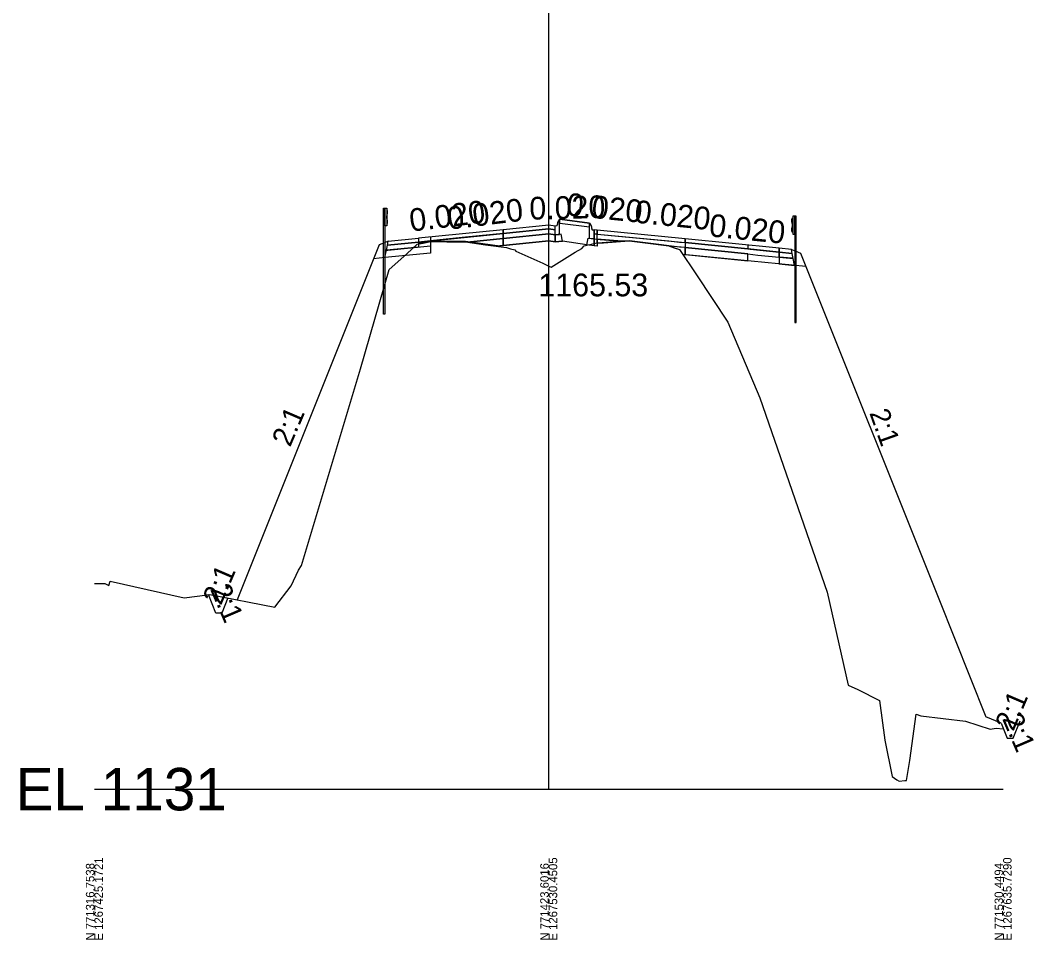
# Model space of a CAD drawing. Extents: x -3833 to 1267678, y -522 to 773248.
# Drawn here: x 4657.2 to 4991.8, y -49.7 to 253.8 of the extents above; entities that cross this region are included whole.
import ezdxf

# ---------------------------------------------------------------- set-up
doc = ezdxf.new("R2010")
doc.units = 0
for name, color, linetype in [('Exist Utilities Water UG Line SUE LOS B', 7, 'Continuous'), ('Prop Drainage Structure Catch Basin Grate 840 03E CELL', 7, 'Continuous'), ('Prop Drainage Structure Catch Basin Grate 840 03E Label', 7, 'Continuous'), ('Prop Drainage Structure Catch Basin Grate 840 03F CELL', 7, 'Continuous'), ('Prop Drainage Structure Catch Basin Grate 840 03F Label', 7, 'Continuous'), ('Prop Drainage Structure Catch Basin Grate 840 03G CELL', 7, 'Continuous'), ('Prop Drainage Structure Catch Basin Grate 840 03G Label', 7, 'Continuous'), ('Prop Drainage Structure Drop Inlet Grate 2 Narrow Slots and Flat Grates 840 29 CELL', 7, 'Continuous'), ('Prop Drainage Structure Drop Inlet Grate 2 Narrow Slots and Flat Grates 840 29 Label', 7, 'Continuous'), ('Prop Drainage Structure Headwall CELL', 7, 'Continuous'), ('Prop Drainage Structure Junction Box with Manhole CELL', 7, 'Continuous'), ('Prop Drainage Structure Junction Box with Manhole Label', 7, 'Continuous'), ('Prop Drainage Structure Junction Box with Manhole TB Label', 7, 'Continuous'), ('Prop Drainage Structure Pipe RCP 18in Class III', 7, 'Continuous'), ('Prop Drainage Structure Pipe RCP 18in Class III Label', 7, 'Continuous'), ('Prop Drainage Structure Pipe Removal', 7, 'Continuous'), ('Prop Drainage Structure Removal Label', 7, 'Continuous'), ('Prop Earthen Structure Ditch Flow Line', 7, 'Continuous'), ('Scratch_Level_3', 7, 'Continuous')]:
    doc.layers.add(name, color=color, linetype=linetype)

msp = doc.modelspace()

# ---------------------------------------------------------------- linework, layer by layer
at = {"layer": 'Prop Drainage Structure Catch Basin Grate 840 03F CELL'}
for p, q in [((4835.26, 188.09), (4835.35, 188.08)), ((4835.35, 188.08), (4845.16, 186.8)), ((4845.16, 186.8), (4845.16, 186.8)), ((4778.67, 180.84), (4777.47, 180.37)), ((4775.67, 179.64), (4728.82, 62.51)), ((4777.47, 180.37), (4775.67, 179.64)), ((4911.8, 178.13), (4913, 177.65)), ((4913, 177.65), (4914.8, 176.93)), ((4914.8, 176.93), (4960.45, 62.81)), ((4721.74, 58.12), (4719.3, 64.22)), ((4725.74, 63.12), (4723.74, 58.12)), ((4960.45, 62.81), (4976.02, 23.88)), ((4723.74, 58.12), (4721.74, 58.12)), ((4981.02, 21.79), (4976.02, 23.88)), ((4981.02, 21.79), (4983.02, 16.79)), ((4985.02, 16.79), (4987.32, 22.53)), ((4983.02, 16.79), (4985.02, 16.79))]:
    msp.add_line(p, q, dxfattribs=at)
at = {"layer": 'Prop Drainage Structure Catch Basin Grate 840 03F Label'}
for p, q in [((4792.67, 180.99), (4788.67, 180.59)), ((4788.67, 180.21), (4792.61, 180.91)), ((4792.61, 180.91), (4793.67, 180.91)), ((4793.67, 181.09), (4792.67, 180.99)), ((4804.23, 182.15), (4793.67, 181.09)), ((4793.67, 181.09), (4793.67, 181.09)), ((4793.67, 180.91), (4793.67, 180.91)), ((4793.67, 180.91), (4804.23, 180.86)), ((4816.67, 183.39), (4804.23, 182.15)), ((4804.23, 182.15), (4804.23, 182.15)), ((4804.23, 182.15), (4804.23, 182.15)), ((4804.23, 180.86), (4804.23, 180.86)), ((4804.23, 180.86), (4804.23, 180.86)), ((4804.23, 180.86), (4805.81, 180.64)), ((4805.81, 180.64), (4816.67, 181.73)), ((4816.67, 181.73), (4816.67, 183.39)), ((4816.67, 183.39), (4816.67, 183.39)), ((4816.67, 181.73), (4816.67, 181.73)), ((4847.65, 181.55), (4847.65, 183.22)), ((4847.65, 183.22), (4847.65, 183.22)), ((4847.65, 183.22), (4847.65, 183.22)), ((4847.65, 183.22), (4855.98, 182.46)), ((4855.77, 180.82), (4847.65, 181.55)), ((4847.65, 181.55), (4847.65, 181.55)), ((4847.65, 181.55), (4847.65, 181.55)), ((4847.65, 181.55), (4847.65, 181.55)), ((4847.65, 181.55), (4847.65, 181.55)), ((4855.98, 180.83), (4855.77, 180.82)), ((4855.98, 182.46), (4855.98, 182.46)), ((4855.98, 182.46), (4858.31, 182.23)), ((4858.31, 181.02), (4855.98, 180.83)), ((4855.98, 180.83), (4855.98, 180.83)), ((4858.31, 182.23), (4858.31, 182.23)), ((4858.31, 182.23), (4868.88, 181.17)), ((4868.88, 179.63), (4858.31, 181.02)), ((4858.31, 181.02), (4858.31, 181.02)), ((4868.88, 181.17), (4868.88, 181.17)), ((4868.88, 181.17), (4871.31, 180.93)), ((4871.31, 180.93), (4871.31, 180.93)), ((4871.31, 180.93), (4871.31, 180.93)), ((4871.31, 180.93), (4872.2, 180.84)), ((4872.2, 180.84), (4872.2, 180.84)), ((4872.2, 180.84), (4874.88, 180.57)), ((4778.07, 177.87), (4778.41, 179.57)), ((4788.67, 178.93), (4778.07, 177.87)), ((4778.07, 177.87), (4778.07, 177.87)), ((4778.07, 177.87), (4778.07, 177.87)), ((4778.41, 179.57), (4788.67, 180.59)), ((4778.41, 179.57), (4778.41, 179.57)), ((4788.67, 180.59), (4788.67, 178.93)), ((4788.67, 180.59), (4788.67, 180.21)), ((4788.67, 180.21), (4788.67, 180.21)), ((4788.67, 178.93), (4788.67, 178.93)), ((4805.81, 180.64), (4805.81, 180.64)), ((4805.81, 180.64), (4805.81, 180.64)), ((4871.31, 179.31), (4868.88, 179.63)), ((4868.88, 179.63), (4868.88, 179.63)), ((4871.51, 179.24), (4871.31, 179.31)), ((4871.31, 179.31), (4871.31, 179.31)), ((4871.31, 179.31), (4871.31, 179.31)), ((4872.2, 179.17), (4871.51, 179.24)), ((4871.51, 179.24), (4871.51, 179.24)), ((4874.88, 178.9), (4872.2, 179.17)), ((4872.2, 179.17), (4872.2, 179.17)), ((4874.88, 180.57), (4876.67, 180.39)), ((4876.67, 178.73), (4874.88, 178.9)), ((4876.67, 180.39), (4876.67, 180.39)), ((4876.67, 180.39), (4876.67, 178.73)), ((4876.67, 178.73), (4876.67, 178.73)), ((4876.67, 178.73), (4876.67, 178.73)), ((4907.73, 177.29), (4907.73, 175.64)), ((4912.06, 176.85), (4907.73, 177.29)), ((4907.73, 175.64), (4912.39, 175.17)), ((4912.39, 175.17), (4912.06, 176.85))]:
    msp.add_line(p, q, dxfattribs=at)
at = {"layer": 'Prop Drainage Structure Catch Basin Grate 840 03G CELL'}
for p, q in [((4777.6, 175.53), (4778.07, 177.87)), ((4778.07, 177.87), (4778.57, 177.92)), ((4778.57, 177.92), (4792.67, 179.33)), ((4792.67, 176.86), (4777.6, 175.53)), ((4907.73, 175.64), (4907.73, 173.34)), ((4911.89, 175.22), (4907.73, 175.64)), ((4912.39, 175.17), (4911.89, 175.22)), ((4912.86, 172.83), (4912.39, 175.17)), ((4907.73, 173.34), (4912.86, 172.83))]:
    msp.add_line(p, q, dxfattribs=at)
at = {"layer": 'Prop Drainage Structure Catch Basin Grate 840 03G Label'}
for p, q in [((4816.67, 184.64), (4816.67, 183.39)), ((4792.67, 182.24), (4792.67, 180.99)), ((4897.37, 179.57), (4897.37, 178.32))]:
    msp.add_line(p, q, dxfattribs=at)
at = {"layer": 'Prop Drainage Structure Drop Inlet Grate 2 Narrow Slots and Flat Grates 840 29 CELL'}
for p, q in [((4831.67, 0), (4831.67, 543.04)), ((4681.67, 0), (4831.67, 0)), ((4831.67, 0), (4981.67, 0))]:
    msp.add_line(p, q, dxfattribs=at)
at = {"layer": 'Prop Drainage Structure Drop Inlet Grate 2 Narrow Slots and Flat Grates 840 29 Label'}
msp.add_lwpolyline([(4681.67, 67.87), (4685.08, 67.9), (4686.41, 67.2), (4686.83, 68.69), (4711.32, 63.17), (4715.59, 63.71), (4719.78, 64.29), (4741.23, 60.07), (4746.62, 67.08), (4749.07, 72.32), (4750.02, 73.84), (4769.57, 138.75), (4778.99, 171.55), (4784.84, 176.67), (4788.2, 179.85), (4790.17, 180.2), (4792.59, 180.71), (4797.99, 180.69), (4804.16, 180.64), (4810.82, 179.7), (4817.76, 178.73), (4819.09, 178.36), (4820.47, 177.99), (4820.86, 177.52), (4829.67, 173.63), (4831.67, 172.67), (4832.51, 172.27), (4840.38, 177.23), (4842.55, 178.49), (4843.36, 179.33), (4846.15, 179.96), (4847.07, 180.16), (4849.79, 180.37), (4858.18, 181.01), (4862.6, 180.48), (4871.31, 179.33), (4873.11, 178.68), (4874.88, 178.08), (4880.41, 169.77), (4890.78, 154.15), (4901.31, 129.2), (4923.57, 65.04), (4930.56, 34.37), (4933.69, 32.87), (4940.89, 29.24), (4942.62, 16.15), (4945.03, 4.22), (4946.54, 3.08), (4947.36, 2.64), (4949.25, 2.86), (4949.83, 2.83), (4950.89, 9.44), (4953.02, 24.71), (4954.47, 24.18), (4969.23, 22.42), (4977.37, 19.82), (4979.39, 20.14), (4981.67, 19.86)], dxfattribs=at)
at = {"layer": 'Prop Drainage Structure Headwall CELL'}
for p, q in [((4831.67, 186.14), (4816.67, 184.64)), ((4816.67, 183.39), (4831.67, 184.89)), ((4816.67, 184.64), (4816.67, 184.64)), ((4816.67, 184.64), (4816.67, 183.39)), ((4833.76, 185.86), (4831.67, 186.14)), ((4831.67, 184.89), (4833.76, 184.61)), ((4833.76, 184.61), (4833.76, 185.86)), ((4833.76, 185.86), (4833.76, 185.86)), ((4833.76, 184.61), (4833.76, 184.61)), ((4833.76, 184.61), (4833.76, 184.61)), ((4846.66, 184.57), (4846.66, 183.32)), ((4847.65, 184.47), (4846.66, 184.57)), ((4847.65, 183.22), (4847.65, 184.47)), ((4847.65, 184.47), (4847.65, 184.47)), ((4778.41, 179.57), (4778.67, 180.84)), ((4778.67, 180.84), (4788.67, 181.84)), ((4778.67, 180.84), (4778.67, 180.84)), ((4788.67, 181.84), (4788.67, 180.59)), ((4816.67, 183.39), (4816.67, 183.39)), ((4816.67, 183.39), (4816.67, 183.39)), ((4846.66, 183.32), (4847.65, 183.22)), ((4788.67, 180.59), (4778.41, 179.57)), ((4778.41, 179.57), (4778.41, 179.57)), ((4778.41, 179.57), (4778.41, 179.57)), ((4788.67, 180.59), (4788.67, 180.59)), ((4907.73, 178.54), (4907.73, 177.29)), ((4911.8, 178.13), (4907.73, 178.54)), ((4912.06, 176.85), (4911.8, 178.13)), ((4907.73, 177.29), (4912.06, 176.85))]:
    msp.add_line(p, q, dxfattribs=at)
at = {"layer": 'Prop Drainage Structure Junction Box with Manhole CELL'}
for p, q in [((4815.49, 181.61), (4805.81, 180.64)), ((4816.67, 181.73), (4815.49, 181.61)), ((4831.67, 183.24), (4816.67, 181.73)), ((4816.67, 181.73), (4816.67, 181.74)), ((4816.67, 181.74), (4816.68, 179.43)), ((4816.67, 181.73), (4816.67, 181.73)), ((4816.68, 179.43), (4816.67, 181.73)), ((4816.67, 181.73), (4816.67, 181.73)), ((4816.67, 181.73), (4816.67, 181.73)), ((4816.68, 179.43), (4831.67, 180.95)), ((4833.76, 182.95), (4831.67, 183.24)), ((4831.67, 180.95), (4833.75, 180.65)), ((4833.75, 180.65), (4833.76, 182.95)), ((4833.76, 182.95), (4833.75, 180.65)), ((4833.75, 180.65), (4836.18, 180.84)), ((4835.76, 183.14), (4833.76, 182.95)), ((4833.76, 182.95), (4833.76, 182.95)), ((4833.76, 182.95), (4833.76, 182.95)), ((4836.18, 180.84), (4835.76, 183.14)), ((4844.21, 179.68), (4844.66, 181.85)), ((4844.66, 181.85), (4846.66, 181.65)), ((4846.65, 179.36), (4846.66, 181.65)), ((4846.66, 181.65), (4846.65, 179.36)), ((4846.66, 181.65), (4847.65, 181.55)), ((4847.65, 181.55), (4847.64, 179.26)), ((4847.64, 180.19), (4847.65, 181.55)), ((4847.65, 181.55), (4848.63, 181.45)), ((4848.63, 181.45), (4855.77, 180.82)), ((4855.77, 180.82), (4849.35, 180.32)), ((4805.81, 180.64), (4805.81, 180.64)), ((4805.81, 180.64), (4805.81, 180.64)), ((4805.81, 180.64), (4808.37, 180.3)), ((4808.37, 180.3), (4808.37, 180.3)), ((4808.37, 180.28), (4808.37, 180.28)), ((4808.37, 180.28), (4809.87, 180.07)), ((4809.87, 180.07), (4815.49, 179.29)), ((4815.49, 179.29), (4816.68, 179.43)), ((4816.68, 179.43), (4816.68, 179.43)), ((4816.68, 179.43), (4816.68, 179.43)), ((4816.68, 179.43), (4816.68, 179.43)), ((4816.68, 179.43), (4816.68, 179.43)), ((4816.68, 179.43), (4816.68, 179.43)), ((4833.75, 180.65), (4833.75, 180.65)), ((4833.75, 180.65), (4833.75, 180.65)), ((4833.75, 180.65), (4833.75, 180.65)), ((4833.75, 180.65), (4833.75, 180.65)), ((4846.65, 179.36), (4844.21, 179.68)), ((4844.21, 179.68), (4844.21, 179.68)), ((4847.64, 179.26), (4846.65, 179.36)), ((4849.35, 180.32), (4847.64, 180.19)), ((4875.42, 178.85), (4871.56, 179.24)), ((4871.56, 179.24), (4874.88, 178.1)), ((4874.88, 178.1), (4875.93, 176.52)), ((4876.67, 178.73), (4875.42, 178.85)), ((4876.67, 178.74), (4876.67, 176.45)), ((4897.37, 176.67), (4876.67, 178.74)), ((4876.67, 176.45), (4876.67, 178.73)), ((4875.93, 176.52), (4876.67, 176.45)), ((4876.67, 176.45), (4897.37, 174.38)), ((4897.37, 174.38), (4897.37, 176.67))]:
    msp.add_line(p, q, dxfattribs=at)
at = {"layer": 'Prop Drainage Structure Junction Box with Manhole Label'}
for p, q in [((4831.67, 184.89), (4816.67, 183.39)), ((4833.76, 184.61), (4831.67, 184.89)), ((4833.76, 182.95), (4833.76, 184.61)), ((4833.76, 184.61), (4833.76, 184.61)), ((4816.67, 183.39), (4816.67, 183.39)), ((4816.67, 183.39), (4816.67, 181.74)), ((4816.67, 181.73), (4831.67, 183.24)), ((4816.67, 181.74), (4816.67, 181.74)), ((4816.67, 181.74), (4816.67, 181.73)), ((4816.67, 181.73), (4816.67, 181.73)), ((4831.67, 183.24), (4833.76, 182.95)), ((4833.76, 182.95), (4833.76, 182.95)), ((4833.76, 182.95), (4833.76, 182.95)), ((4833.76, 182.95), (4833.76, 182.95)), ((4846.66, 183.32), (4846.66, 181.65)), ((4847.65, 183.22), (4846.66, 183.32)), ((4846.66, 181.65), (4847.65, 181.55)), ((4847.65, 181.55), (4847.65, 183.22)), ((4847.65, 183.22), (4847.65, 183.22)), ((4847.65, 181.55), (4847.65, 181.55)), ((4876.67, 180.39), (4876.67, 178.74)), ((4897.37, 178.32), (4876.67, 180.39)), ((4876.67, 178.74), (4897.37, 176.67)), ((4907.73, 177.29), (4897.37, 178.32)), ((4897.37, 176.67), (4900.68, 176.28)), ((4900.68, 176.28), (4907.73, 175.64)), ((4907.73, 175.64), (4907.73, 177.29))]:
    msp.add_line(p, q, dxfattribs=at)
at = {"layer": 'Prop Drainage Structure Junction Box with Manhole TB Label'}
for p, q in [((4792.67, 180.91), (4792.67, 176.86)), ((4831.67, 180.95), (4815.49, 179.29)), ((4833.75, 180.65), (4831.67, 180.95)), ((4836.18, 180.84), (4833.75, 180.65)), ((4844.21, 179.68), (4836.18, 180.84)), ((4846.65, 179.36), (4844.21, 179.68)), ((4847.64, 179.26), (4846.65, 179.36)), ((4847.64, 180.19), (4847.64, 179.26)), ((4777.6, 175.53), (4773.82, 175.02)), ((4792.67, 176.86), (4777.6, 175.53)), ((4916.59, 172.46), (4875.93, 176.52))]:
    msp.add_line(p, q, dxfattribs=at)
at = {"layer": 'Prop Drainage Structure Pipe RCP 18in Class III'}
for p, q in [((4777.09, 179.29), (4777.09, 191.79)), ((4777.09, 191.79), (4777.58, 191.79)), ((4777.58, 191.79), (4777.58, 179.24)), ((4777.58, 185.88), (4777.58, 191.79)), ((4777.58, 191.79), (4778.24, 191.79)), ((4778.24, 191.79), (4778.24, 185.88)), ((4778.24, 191.39), (4778.24, 186.28)), ((4778.34, 191.29), (4778.24, 191.39)), ((4778.49, 190.79), (4778.34, 191.29)), ((4778.49, 190.07), (4778.49, 190.79)), ((4778.26, 189.06), (4778.49, 190.07)), ((4778.26, 188.61), (4778.26, 189.06)), ((4778.49, 187.6), (4778.26, 188.61)), ((4778.49, 186.89), (4778.49, 187.6)), ((4911.97, 188.08), (4912.11, 188.58)), ((4911.97, 187.36), (4911.97, 188.08)), ((4911.97, 188.08), (4911.97, 188.08)), ((4912.11, 188.58), (4912.21, 188.68)), ((4912.11, 188.58), (4912.11, 188.58)), ((4912.21, 189.08), (4912.21, 183.17)), ((4912.88, 189.08), (4912.21, 189.08)), ((4912.21, 188.68), (4912.21, 183.57)), ((4912.88, 183.17), (4912.88, 189.08)), ((4912.88, 189.08), (4912.88, 176.53)), ((4913.36, 189.08), (4912.88, 189.08)), ((4913.36, 176.58), (4913.36, 189.08)), ((4778.24, 185.88), (4777.58, 185.88)), ((4778.24, 186.28), (4778.34, 186.39)), ((4778.34, 186.39), (4778.49, 186.89)), ((4912.2, 186.36), (4911.97, 187.36)), ((4911.97, 187.36), (4911.97, 187.36)), ((4911.97, 187.36), (4911.97, 187.36)), ((4911.97, 184.89), (4912.2, 185.9)), ((4911.97, 184.18), (4911.97, 184.89)), ((4911.97, 184.89), (4911.97, 184.89)), ((4912.11, 183.68), (4911.97, 184.18)), ((4911.97, 184.18), (4911.97, 184.18)), ((4911.97, 184.18), (4911.97, 184.18)), ((4912.2, 185.9), (4912.2, 186.36)), ((4912.2, 185.9), (4912.2, 185.9)), ((4912.21, 183.57), (4912.11, 183.68)), ((4912.11, 183.68), (4912.11, 183.68)), ((4912.21, 183.57), (4912.21, 183.57)), ((4912.21, 183.17), (4912.88, 183.17)), ((4777.09, 156.74), (4777.09, 179.29)), ((4777.58, 179.24), (4777.58, 156.74)), ((4912.88, 176.53), (4912.88, 154.03)), ((4913.36, 154.03), (4913.36, 176.58)), ((4777.58, 156.74), (4777.09, 156.74)), ((4912.88, 154.03), (4913.36, 154.03))]:
    msp.add_line(p, q, dxfattribs=at)
at = {"layer": 'Prop Drainage Structure Pipe Removal'}
for p, q in [((4835.35, 188.08), (4835.26, 188.09)), ((4835.26, 188.09), (4835.26, 186.84)), ((4845.16, 186.8), (4835.35, 188.08)), ((4835.26, 186.84), (4835.35, 186.83)), ((4835.35, 186.83), (4845.16, 185.55)), ((4845.16, 185.55), (4845.16, 186.8)), ((4845.16, 186.8), (4845.16, 186.8)), ((4845.16, 185.55), (4845.16, 185.55))]:
    msp.add_line(p, q, dxfattribs=at)
at = {"layer": 'Prop Drainage Structure Removal Label'}
for p, q in [((4835.26, 188.09), (4834.61, 187.01)), ((4835.26, 183.09), (4835.26, 188.09)), ((4834.44, 185.93), (4833.76, 185.86)), ((4833.76, 182.94), (4833.76, 185.86)), ((4834.51, 186.32), (4834.51, 186.24)), ((4845.16, 181.8), (4845.16, 186.8)), ((4845.16, 186.8), (4845.81, 185.72)), ((4845.91, 185.03), (4845.91, 184.95)), ((4845.97, 184.64), (4846.66, 184.57)), ((4846.66, 181.65), (4846.66, 184.57)), ((4833.76, 182.94), (4835.26, 183.09)), ((4846.66, 181.65), (4845.16, 181.8))]:
    msp.add_line(p, q, dxfattribs=at)
for centre, major_axis, start_param, end_param in [((4834.44, 186.24), (0, -0.312), 0.019997, 1.570796), ((4834.65, 186.32), (0, -0.729), 3.463343, 4.712389), ((4845.76, 185.03), (0, 0.729), 4.712389, 5.961435), ((4845.97, 184.95), (0, -0.312), 4.712389, 6.263188)]:
    msp.add_ellipse(centre, major_axis=major_axis, ratio=0.2, start_param=start_param, end_param=end_param, dxfattribs=at)
at = {"layer": 'Prop Earthen Structure Ditch Flow Line'}
for p, q in [((4816.67, 184.64), (4788.67, 181.84)), ((4816.67, 183.39), (4816.67, 184.64)), ((4876.67, 181.64), (4847.65, 184.47)), ((4847.65, 184.47), (4847.65, 183.22)), ((4788.67, 180.59), (4816.67, 183.39)), ((4788.67, 181.84), (4788.67, 181.84)), ((4788.67, 181.84), (4788.67, 180.59)), ((4788.67, 180.59), (4792.67, 180.99)), ((4816.67, 183.39), (4816.67, 183.39)), ((4847.65, 183.22), (4847.65, 183.22)), ((4847.65, 183.22), (4876.67, 180.39)), ((4876.67, 180.39), (4876.67, 181.64)), ((4876.67, 181.64), (4876.67, 181.64)), ((4876.67, 181.64), (4876.67, 180.39)), ((4907.73, 178.54), (4876.67, 181.64)), ((4788.67, 180.59), (4788.67, 180.59)), ((4876.67, 180.39), (4876.67, 180.39)), ((4876.67, 180.39), (4876.67, 180.39)), ((4876.67, 180.39), (4897.37, 178.32)), ((4897.37, 178.32), (4898.18, 178.22)), ((4898.18, 178.22), (4907.73, 177.29)), ((4907.73, 177.29), (4907.73, 178.54))]:
    msp.add_line(p, q, dxfattribs=at)

# ---------------------------------------------------------------- texts
at = {"layer": 'Exist Utilities Water UG Line SUE LOS B'}
for height, rotation, p in [(7.498, 6.9522, (4786.14, 183.99)), (7.498, 6.9522, (4798.65, 184.63)), (7.5, 1.3462, (4825.35, 187.95)), (7.499, 354.2894, (4837.26, 189.41)), (7.499, 354.2894, (4859.73, 187.02)), (7.499, 354.2894, (4884.38, 182.48))]:
    msp.add_text('0.020', height=height, rotation=rotation, dxfattribs=at).set_placement(p)
at = {"layer": 'Prop Drainage Structure Catch Basin Grate 840 03E CELL'}
msp.add_text('1165.53', height=7.5, dxfattribs=at).set_placement((4828.25, 162.67))
at = {"layer": 'Prop Drainage Structure Catch Basin Grate 840 03E Label'}
for p in [(4816.67, 184.64), (4816.67, 184.64), (4831.67, 186.14), (4845.92, 184.72), (4846.67, 184.64), (4846.67, 184.64), (4782.67, 181.24), (4792.67, 182.24), (4792.67, 182.24), (4897.37, 179.57), (4901.44, 179.16), (4906.63, 177.09), (4908.44, 176.36), (4725.74, 63.12)]:
    msp.add_text('X', height=0.00125, dxfattribs=at).set_placement(p)
at = {"layer": 'Prop Drainage Structure Drop Inlet Grate 2 Narrow Slots and Flat Grates 840 29 CELL'}
msp.add_text('EL 1131', height=14, dxfattribs=at).set_placement((4655.67, -7))
for s, p in [('E 1267425.1721', (4684.47, -50)), ('E 1267530.4505', (4834.47, -50)), ('E 1267635.7290', (4984.47, -50)), ('N 771316.7538', (4681.67, -50)), ('N 771423.6016', (4831.67, -50)), ('N 771530.4494', (4981.67, -50))]:
    msp.add_text(s, height=2.8, rotation=90, dxfattribs=at).set_placement(p)
at = {"layer": 'Prop Drainage Structure Pipe RCP 18in Class III Label'}
msp.add_text('2:1', height=6.581, rotation=289.6124, dxfattribs=at).set_placement((4937.46, 124.2))
at = {"layer": 'Scratch_Level_3'}
for rotation, p in [(66.7255, (4746.27, 112.64)), (66.7255, (4723.45, 60.43)), (293.2745, (4719.82, 66)), (66.7255, (4985.04, 18.86)), (293.2745, (4981.28, 23.29))]:
    msp.add_text('2:1', height=6.83, rotation=rotation, dxfattribs=at).set_placement(p)

doc.saveas('drawing.dxf')
